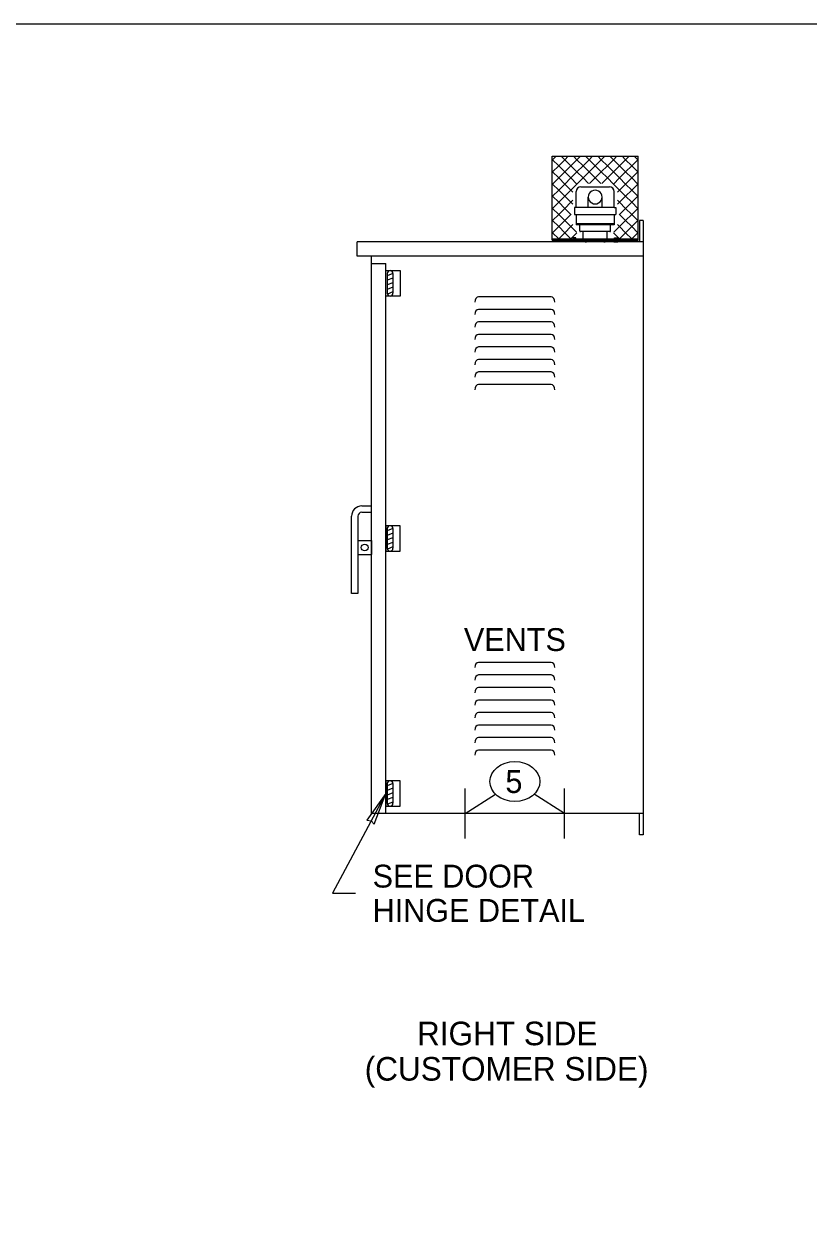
# Model space of a CAD drawing. Extents: x 99862 to 103680, y 99470 to 105076.
# Drawn here: x 101069 to 101618, y 101236 to 102076 of the extents above; entities that cross this region are included whole.
import ezdxf

# ---------------------------------------------------------------- set-up
doc = ezdxf.new("R2010")
doc.units = 0
for name, color, linetype in [('Level 1', 7, 'Continuous'), ('Level 11', 7, 'Continuous'), ('Level 15', 7, 'Continuous'), ('Level 20', 7, 'Continuous'), ('Level 40', 7, 'Continuous')]:
    doc.layers.add(name, color=color, linetype=linetype)

msp = doc.modelspace()

# ---------------------------------------------------------------- linework, layer by layer
at = {"layer": 'Level 1'}
for p, q in [((101438.48, 101925.19), (101438.48, 101982.95)), ((101438.48, 101982.94), (101498.48, 101982.94)), ((101438.48, 101980.71), (101438.7, 101980.49)), ((101438.7, 101980.49), (101438.48, 101980.27)), ((101438.7, 101980.49), (101441.16, 101982.94)), ((101442.96, 101976.24), (101438.7, 101980.49)), ((101438.7, 101971.98), (101442.96, 101976.24)), ((101447.21, 101980.49), (101442.96, 101976.24)), ((101442.96, 101976.24), (101447.21, 101971.98)), ((101447.21, 101980.49), (101444.76, 101982.94)), ((101449.66, 101982.94), (101447.21, 101980.49)), ((101451.47, 101976.24), (101447.21, 101980.49)), ((101447.21, 101971.98), (101451.47, 101976.24)), ((101455.72, 101980.49), (101451.47, 101976.24)), ((101451.47, 101976.24), (101455.72, 101971.98)), ((101453.27, 101982.94), (101455.72, 101980.49)), ((101455.72, 101980.49), (101458.17, 101982.94)), ((101459.98, 101976.24), (101455.72, 101980.49)), ((101455.72, 101971.98), (101459.98, 101976.24)), ((101464.23, 101980.49), (101459.98, 101976.24)), ((101459.98, 101976.24), (101464.23, 101971.98)), ((101461.78, 101982.94), (101464.23, 101980.49)), ((101464.23, 101980.49), (101466.68, 101982.94)), ((101468.48, 101976.24), (101464.23, 101980.49)), ((101464.23, 101971.98), (101468.48, 101976.24)), ((101472.74, 101980.49), (101468.48, 101976.24)), ((101468.48, 101976.24), (101472.74, 101971.98)), ((101470.29, 101982.94), (101472.74, 101980.49)), ((101472.74, 101980.49), (101475.19, 101982.94)), ((101476.99, 101976.24), (101472.74, 101980.49)), ((101472.74, 101971.98), (101476.99, 101976.24)), ((101481.25, 101980.49), (101476.99, 101976.24)), ((101476.99, 101976.24), (101481.25, 101971.98)), ((101478.79, 101982.94), (101481.25, 101980.49)), ((101481.25, 101980.49), (101483.7, 101982.94)), ((101485.5, 101976.24), (101481.25, 101980.49)), ((101481.25, 101971.98), (101485.5, 101976.24)), ((101489.75, 101980.49), (101485.5, 101976.24)), ((101485.5, 101976.24), (101489.75, 101971.98)), ((101487.3, 101982.94), (101489.75, 101980.49)), ((101492.21, 101982.94), (101489.75, 101980.49)), ((101489.75, 101980.49), (101494.01, 101976.24)), ((101494.01, 101976.24), (101489.75, 101971.98)), ((101494.01, 101976.24), (101498.26, 101980.49)), ((101498.26, 101971.98), (101494.01, 101976.24)), ((101498.26, 101980.49), (101495.81, 101982.94)), ((101498.48, 101980.71), (101498.26, 101980.49)), ((101498.26, 101980.49), (101498.48, 101980.27)), ((101498.48, 101925.19), (101498.48, 101982.94)), ((101438.48, 101972.2), (101438.7, 101971.98)), ((101438.7, 101971.98), (101438.48, 101971.76)), ((101442.96, 101967.73), (101438.7, 101971.98)), ((101447.21, 101971.98), (101442.96, 101967.73)), ((101451.47, 101967.73), (101447.21, 101971.98)), ((101455.72, 101971.98), (101451.47, 101967.73)), ((101459.98, 101967.73), (101455.72, 101971.98)), ((101464.23, 101971.98), (101459.98, 101967.73)), ((101468.48, 101967.73), (101464.23, 101971.98)), ((101472.74, 101971.98), (101468.48, 101967.73)), ((101476.99, 101967.73), (101472.74, 101971.98)), ((101481.25, 101971.98), (101476.99, 101967.73)), ((101485.5, 101967.73), (101481.25, 101971.98)), ((101489.75, 101971.98), (101485.5, 101967.73)), ((101489.75, 101971.98), (101494.01, 101967.73)), ((101494.01, 101967.73), (101498.26, 101971.98)), ((101498.48, 101972.21), (101498.26, 101971.98)), ((101498.26, 101971.98), (101498.48, 101971.76)), ((101438.48, 101963.7), (101438.7, 101963.48)), ((101438.7, 101963.48), (101438.48, 101963.26)), ((101438.7, 101963.48), (101442.96, 101967.73)), ((101442.96, 101959.22), (101438.7, 101963.48)), ((101442.96, 101967.73), (101447.21, 101963.48)), ((101447.21, 101963.48), (101442.96, 101959.22)), ((101447.21, 101963.48), (101451.47, 101967.73)), ((101451.47, 101959.22), (101447.21, 101963.48)), ((101451.47, 101967.73), (101455.72, 101963.48)), ((101455.72, 101963.48), (101451.47, 101959.22)), ((101455.72, 101963.48), (101459.98, 101967.73)), ((101455.94, 101963.26), (101455.72, 101963.48)), ((101458.46, 101961.45), (101478.51, 101961.45)), ((101459.98, 101967.73), (101463.85, 101963.86)), ((101464.61, 101963.86), (101468.48, 101967.73)), ((101468.48, 101967.73), (101472.36, 101963.86)), ((101473.12, 101963.86), (101476.99, 101967.73)), ((101476.99, 101967.73), (101481.25, 101963.48)), ((101481.25, 101963.48), (101481.03, 101963.26)), ((101481.25, 101963.48), (101485.5, 101967.73)), ((101485.5, 101959.22), (101481.25, 101963.48)), ((101485.5, 101967.73), (101489.75, 101963.48)), ((101489.75, 101963.48), (101485.5, 101959.22)), ((101494.01, 101967.73), (101489.75, 101963.48)), ((101489.75, 101963.48), (101494.01, 101959.22)), ((101498.26, 101963.48), (101494.01, 101967.73)), ((101494.01, 101959.22), (101498.26, 101963.48)), ((101498.48, 101963.7), (101498.26, 101963.48)), ((101498.26, 101963.48), (101498.48, 101963.25)), ((101438.48, 101955.19), (101438.7, 101954.97)), ((101438.7, 101954.97), (101438.48, 101954.75)), ((101438.7, 101954.97), (101442.96, 101959.22)), ((101442.96, 101950.71), (101438.7, 101954.97)), ((101442.96, 101959.22), (101447.21, 101954.97)), ((101447.21, 101954.97), (101442.96, 101950.71)), ((101447.21, 101954.97), (101451.47, 101959.22)), ((101451.47, 101950.71), (101447.21, 101954.97)), ((101451.47, 101959.22), (101452.84, 101957.85)), ((101452.84, 101952.09), (101451.47, 101950.71)), ((101455.25, 101947.01), (101455.25, 101958.24)), ((101463.67, 101947.01), (101463.67, 101954.39)), ((101473.3, 101947.01), (101473.3, 101954.39)), ((101481.72, 101947.01), (101481.72, 101958.24)), ((101484.13, 101957.85), (101485.5, 101959.22)), ((101485.5, 101950.71), (101484.13, 101952.09)), ((101485.5, 101959.22), (101489.75, 101954.97)), ((101489.75, 101954.97), (101485.5, 101950.71)), ((101494.01, 101959.22), (101489.75, 101954.97)), ((101489.75, 101954.97), (101494.01, 101950.71)), ((101498.26, 101954.97), (101494.01, 101959.22)), ((101494.01, 101950.71), (101498.26, 101954.97)), ((101498.48, 101955.19), (101498.26, 101954.97)), ((101498.26, 101954.97), (101498.48, 101954.75)), ((101438.48, 101946.68), (101438.7, 101946.46)), ((101438.7, 101946.46), (101438.48, 101946.24)), ((101438.7, 101946.46), (101442.96, 101950.71)), ((101442.96, 101942.2), (101438.7, 101946.46)), ((101442.96, 101950.71), (101447.21, 101946.46)), ((101447.21, 101946.46), (101442.96, 101942.2)), ((101447.21, 101946.46), (101451.47, 101950.71)), ((101451.47, 101942.2), (101447.21, 101946.46)), ((101451.47, 101950.71), (101452.76, 101949.42)), ((101455.25, 101947.01), (101454.04, 101947.01)), ((101454.04, 101947.01), (101454.04, 101942.2)), ((101481.72, 101947.01), (101455.25, 101947.01)), ((101481.72, 101947.01), (101482.92, 101947.01)), ((101482.92, 101947.01), (101482.92, 101942.2)), ((101484.2, 101949.42), (101485.5, 101950.71)), ((101485.5, 101950.71), (101489.75, 101946.46)), ((101489.75, 101946.46), (101485.5, 101942.2)), ((101494.01, 101950.71), (101489.75, 101946.46)), ((101489.75, 101946.46), (101494.01, 101942.2)), ((101498.26, 101946.46), (101494.01, 101950.71)), ((101494.01, 101942.2), (101498.26, 101946.46)), ((101498.48, 101946.68), (101498.26, 101946.46)), ((101498.26, 101946.46), (101498.48, 101946.24)), ((101438.48, 101938.17), (101438.7, 101937.95)), ((101438.7, 101937.95), (101438.48, 101937.73)), ((101438.7, 101937.95), (101442.96, 101942.2)), ((101442.96, 101933.7), (101438.7, 101937.95)), ((101442.96, 101942.2), (101447.21, 101937.95)), ((101447.21, 101937.95), (101442.96, 101933.7)), ((101447.21, 101937.95), (101451.47, 101942.2)), ((101451.47, 101933.7), (101447.21, 101937.95)), ((101451.64, 101942.38), (101451.47, 101942.2)), ((101451.47, 101942.2), (101451.64, 101942.03)), ((101452.84, 101935.07), (101451.47, 101933.7)), ((101454.04, 101942.2), (101482.92, 101942.2)), ((101455.25, 101942.2), (101455.25, 101934.98)), ((101481.72, 101935.58), (101455.25, 101935.58)), ((101481.72, 101934.98), (101455.25, 101934.98)), ((101457.65, 101930.77), (101457.65, 101934.98)), ((101479.31, 101930.77), (101479.31, 101934.98)), ((101481.72, 101942.2), (101481.72, 101934.98)), ((101485.5, 101933.7), (101484.13, 101935.07)), ((101485.5, 101942.2), (101485.33, 101942.38)), ((101485.33, 101942.03), (101485.5, 101942.2)), ((101485.5, 101942.2), (101489.75, 101937.95)), ((101489.75, 101937.95), (101485.5, 101933.7)), ((101494.01, 101942.2), (101489.75, 101937.95)), ((101489.75, 101937.95), (101494.01, 101933.7)), ((101498.26, 101937.95), (101494.01, 101942.2)), ((101494.01, 101933.7), (101498.26, 101937.95)), ((101498.48, 101938.17), (101498.26, 101937.95)), ((101498.26, 101937.95), (101498.48, 101937.73)), ((101438.48, 101929.66), (101438.7, 101929.44)), ((101438.7, 101929.44), (101438.48, 101929.22)), ((101438.7, 101929.44), (101442.96, 101933.7)), ((101442.96, 101925.19), (101438.7, 101929.44)), ((101442.96, 101933.7), (101447.21, 101929.44)), ((101447.21, 101929.44), (101442.96, 101925.19)), ((101447.21, 101929.44), (101451.47, 101933.7)), ((101451.47, 101925.19), (101447.21, 101929.44)), ((101451.47, 101933.7), (101455.43, 101929.73)), ((101455.61, 101929.33), (101451.47, 101925.19)), ((101478.71, 101930.16), (101458.26, 101930.16)), ((101460.06, 101925.35), (101460.06, 101930.16)), ((101476.91, 101925.35), (101476.91, 101930.16)), ((101485.5, 101925.19), (101481.36, 101929.33)), ((101481.54, 101929.73), (101485.5, 101933.7)), ((101485.5, 101933.7), (101489.75, 101929.44)), ((101489.75, 101929.44), (101485.5, 101925.19)), ((101494.01, 101933.7), (101489.75, 101929.44)), ((101489.75, 101929.44), (101494.01, 101925.19)), ((101498.26, 101929.44), (101494.01, 101933.7)), ((101494.01, 101925.19), (101498.26, 101929.44)), ((101498.48, 101929.66), (101498.26, 101929.44)), ((101498.26, 101929.44), (101498.48, 101929.22)), ((101438.48, 101925.19), (101498.48, 101925.19)), ((101438.48, 101924.15), (101438.48, 101925.09)), ((101438.48, 101925.09), (101498.48, 101925.09)), ((101438.48, 101924.15), (101498.48, 101924.15)), ((101474.5, 101922.94), (101462.47, 101922.94)), ((101498.48, 101924.15), (101498.48, 101925.09)), ((101321.98, 101885.1), (101321.98, 101902.87)), ((101322.98, 101900.87), (101322.98, 101887.1)), ((101326.98, 101900.87), (101322.98, 101899.33)), ((101326.98, 101900.87), (101326.98, 101887.1)), ((101326.98, 101897.66), (101322.98, 101896.11)), ((101326.98, 101894.44), (101322.98, 101892.9)), ((101326.98, 101891.23), (101322.98, 101889.68)), ((101326.98, 101888.01), (101323.08, 101886.5)), ((101305.25, 101738.17), (101311.98, 101738.17)), ((101305.25, 101733.73), (101311.98, 101733.73)), ((101298, 101676.86), (101298, 101730.92)), ((101302.43, 101730.92), (101302.43, 101676.86)), ((101321.98, 101724.33), (101321.98, 101706.56)), ((101322.98, 101722.33), (101322.98, 101708.56)), ((101326.98, 101722.33), (101322.98, 101720.79)), ((101326.98, 101719.11), (101322.98, 101717.57)), ((101326.98, 101715.9), (101322.98, 101714.36)), ((101326.98, 101722.33), (101326.98, 101708.56)), ((101302.43, 101714.07), (101311.98, 101714.07)), ((101311.98, 101714.07), (101311.98, 101704.07)), ((101326.98, 101712.68), (101322.98, 101711.14)), ((101326.98, 101709.47), (101323.08, 101707.96)), ((101302.43, 101704.07), (101311.98, 101704.07)), ((101302.43, 101676.86), (101298, 101676.86)), ((101321.98, 101545.79), (101321.98, 101528.02)), ((101322.98, 101543.79), (101322.98, 101530.02)), ((101326.98, 101543.79), (101322.98, 101542.24)), ((101326.98, 101540.57), (101322.98, 101539.03)), ((101326.98, 101543.79), (101326.98, 101530.02)), ((101326.98, 101537.36), (101322.98, 101535.81)), ((101326.98, 101534.14), (101322.98, 101532.6)), ((101326.98, 101530.93), (101323.08, 101529.42))]:
    msp.add_line(p, q, dxfattribs=at)
msp.add_lwpolyline([(99862, 99999.5), (103151, 99999.5), (103151, 102075.5), (99862, 102075.5)], close=True, dxfattribs=at)
for points in [[(101321.98, 101902.87), (101331.98, 101902.87), (101331.98, 101885.1), (101321.98, 101885.1)], [(101321.98, 101706.56), (101331.98, 101706.56), (101331.98, 101724.33), (101321.98, 101724.33)], [(101321.98, 101528.02), (101331.98, 101528.02), (101331.98, 101545.79), (101321.98, 101545.79)]]:
    msp.add_lwpolyline(points, dxfattribs=at)
msp.add_circle((101307.21, 101709.07), 2.37, dxfattribs=at)
for centre, radius, start, end in [((101458.46, 101958.24), 3.21, 90, 180), ((101478.51, 101958.24), 3.21, 0, 90), ((101468.48, 101954.39), 4.81, 0, 180.00029), ((101468.48, 101954.39), 4.81, 179.99971, 360), ((101458.26, 101930.77), 0.602, 180, 270), ((101478.71, 101930.77), 0.602, 270, 0), ((101462.47, 101925.35), 2.41, 180, 270), ((101474.5, 101925.35), 2.41, 270, 0), ((101324.98, 101900.87), 2, 90, 180), ((101324.98, 101900.87), 2, 0, 90), ((101324.98, 101887.1), 2, 180, 270), ((101324.98, 101887.1), 2, 270, 0), ((101305.25, 101730.92), 7.25, 90, 180), ((101305.25, 101730.92), 2.82, 90, 180), ((101324.98, 101722.33), 2, 90, 180), ((101324.98, 101722.33), 2, 0, 90), ((101324.98, 101708.56), 2, 180, 270), ((101324.98, 101708.56), 2, 270, 0), ((101324.98, 101543.79), 2, 90, 180), ((101324.98, 101543.79), 2, 0, 90), ((101324.98, 101530.02), 2, 180, 270), ((101324.98, 101530.02), 2, 270, 0)]:
    msp.add_arc(centre, radius, start, end, dxfattribs=at)
at = {"layer": 'Level 11'}
for p, q in [((101437.71, 101884.5), (101386.8, 101884.5)), ((101437.71, 101875.73), (101386.8, 101875.73)), ((101437.71, 101866.97), (101386.8, 101866.97)), ((101437.71, 101858.21), (101386.8, 101858.21)), ((101437.71, 101849.44), (101386.8, 101849.44)), ((101437.71, 101840.68), (101386.8, 101840.68)), ((101437.71, 101831.92), (101386.8, 101831.92)), ((101437.71, 101823.15), (101386.8, 101823.15)), ((101437.71, 101628.62), (101386.8, 101628.62)), ((101437.71, 101619.85), (101386.8, 101619.85)), ((101437.71, 101611.09), (101386.8, 101611.09)), ((101437.71, 101602.33), (101386.8, 101602.33)), ((101437.71, 101593.56), (101386.8, 101593.56)), ((101437.71, 101584.8), (101386.8, 101584.8)), ((101437.71, 101576.04), (101386.8, 101576.04)), ((101437.71, 101567.27), (101386.8, 101567.27))]:
    msp.add_line(p, q, dxfattribs=at)
for centre, start_param, end_param in [((101386.8, 101880.86), 0, 1.570796), ((101437.71, 101880.86), 4.712389, 6.283185), ((101386.8, 101872.1), 0, 1.570796), ((101437.71, 101872.1), 4.712389, 6.283185), ((101386.8, 101863.33), 0, 1.570796), ((101437.71, 101863.33), 4.712389, 6.283185), ((101386.8, 101854.57), 0, 1.570796), ((101437.71, 101854.57), 4.712389, 6.283185), ((101386.8, 101845.81), 0, 1.570796), ((101437.71, 101845.81), 4.712389, 6.283185), ((101386.8, 101837.04), 0, 1.570796), ((101437.71, 101837.04), 4.712389, 6.283185), ((101386.8, 101828.28), 0, 1.570796), ((101437.71, 101828.28), 4.712389, 6.283185), ((101386.8, 101819.51), 0, 1.570796), ((101437.71, 101819.51), 4.712389, 6.283185), ((101386.8, 101624.98), 0, 1.570796), ((101437.71, 101624.98), 4.712389, 6.283185), ((101386.8, 101616.22), 0, 1.570796), ((101437.71, 101616.22), 4.712389, 6.283185), ((101386.8, 101607.45), 0, 1.570796), ((101437.71, 101607.45), 4.712389, 6.283185), ((101386.8, 101598.69), 0, 1.570796), ((101437.71, 101598.69), 4.712389, 6.283185), ((101386.8, 101589.93), 0, 1.570796), ((101437.71, 101589.93), 4.712389, 6.283185), ((101386.8, 101581.16), 0, 1.570796), ((101437.71, 101581.16), 4.712389, 6.283185), ((101386.8, 101572.4), 0, 1.570796), ((101437.71, 101572.4), 4.712389, 6.283185), ((101386.8, 101563.63), 0, 1.570796), ((101437.71, 101563.63), 4.712389, 6.283185)]:
    msp.add_ellipse(centre, major_axis=(0, 3.64), ratio=0.707107, start_param=start_param, end_param=end_param, dxfattribs=at)
at = {"layer": 'Level 15'}
for p, q in [((101501.98, 101937.94), (101499.48, 101937.94)), ((101499.48, 101937.94), (101499.48, 101922.94)), ((101501.98, 101912.94), (101301.98, 101912.94)), ((101311.98, 101907.94), (101321.98, 101907.94)), ((101321.98, 101522.94), (101321.98, 101907.94)), ((101377.53, 101505.44), (101377.53, 101540.44)), ((101446.98, 101505.44), (101446.98, 101540.44)), ((101321.98, 101536.9), (101284.74, 101467.06)), ((101377.53, 101522.94), (101398.62, 101536.5)), ((101446.98, 101522.94), (101425.9, 101536.5)), ((101499.48, 101507.94), (101499.48, 101522.94)), ((101501.98, 101507.94), (101499.48, 101507.94)), ((101284.74, 101467.06), (101300.74, 101467.06))]:
    msp.add_line(p, q, dxfattribs=at)
msp.add_lwpolyline([(101321.98, 101536.9), (101308.61, 101518.16), (101311.74, 101517.69), (101313.88, 101515.35)], close=True, dxfattribs=at)
at = {"layer": 'Level 20'}
msp.add_ellipse((101412.26, 101545.27), major_axis=(-17.5, 0), ratio=0.8, dxfattribs=at)
at = {"layer": 'Level 40'}
for p, q in [((101501.98, 101937.94), (101501.98, 101507.94)), ((101501.98, 101922.94), (101301.98, 101922.94)), ((101301.98, 101912.94), (101301.98, 101922.94)), ((101311.98, 101522.94), (101311.98, 101912.94)), ((101501.98, 101522.94), (101311.98, 101522.94))]:
    msp.add_line(p, q, dxfattribs=at)
for points in [[(101455.03, 101925.11), (101455.03, 101925.88), (101453.06, 101925.88), (101453.06, 101925.11)], [(101481.94, 101925.11), (101481.94, 101925.88), (101483.91, 101925.88), (101483.91, 101925.11)], [(101455.39, 101923.19), (101455.39, 101922.94), (101452.7, 101922.94), (101452.7, 101923.19)], [(101455.36, 101923.35), (101455.36, 101923.19), (101452.73, 101923.19), (101452.73, 101923.35)], [(101455.03, 101923.35), (101455.03, 101924.15), (101453.06, 101924.15), (101453.06, 101923.35)], [(101481.58, 101923.19), (101481.58, 101922.94), (101484.27, 101922.94), (101484.27, 101923.19)], [(101481.61, 101923.35), (101481.61, 101923.19), (101484.24, 101923.19), (101484.24, 101923.35)], [(101481.94, 101923.35), (101481.94, 101924.15), (101483.91, 101924.15), (101483.91, 101923.35)]]:
    msp.add_lwpolyline(points, close=True, dxfattribs=at)

# ---------------------------------------------------------------- texts
at = {"layer": 'Level 20'}
msp.add_text('VENTS', height=16, rotation=360, dxfattribs=at).set_placement((101376.64, 101636.62))
for s, height, p in [('5', 16, (101405.67, 101537.27)), ('SEE DOOR', 16, (101312.74, 101471.06)), ('HINGE DETAIL', 16, (101312.74, 101447.06)), ('RIGHT SIDE', 16.5, (101343.79, 101360.69)), ('(CUSTOMER SIDE)', 16.5, (101307.21, 101335.94))]:
    msp.add_text(s, height=height, dxfattribs=at).set_placement(p)

doc.saveas('drawing.dxf')
